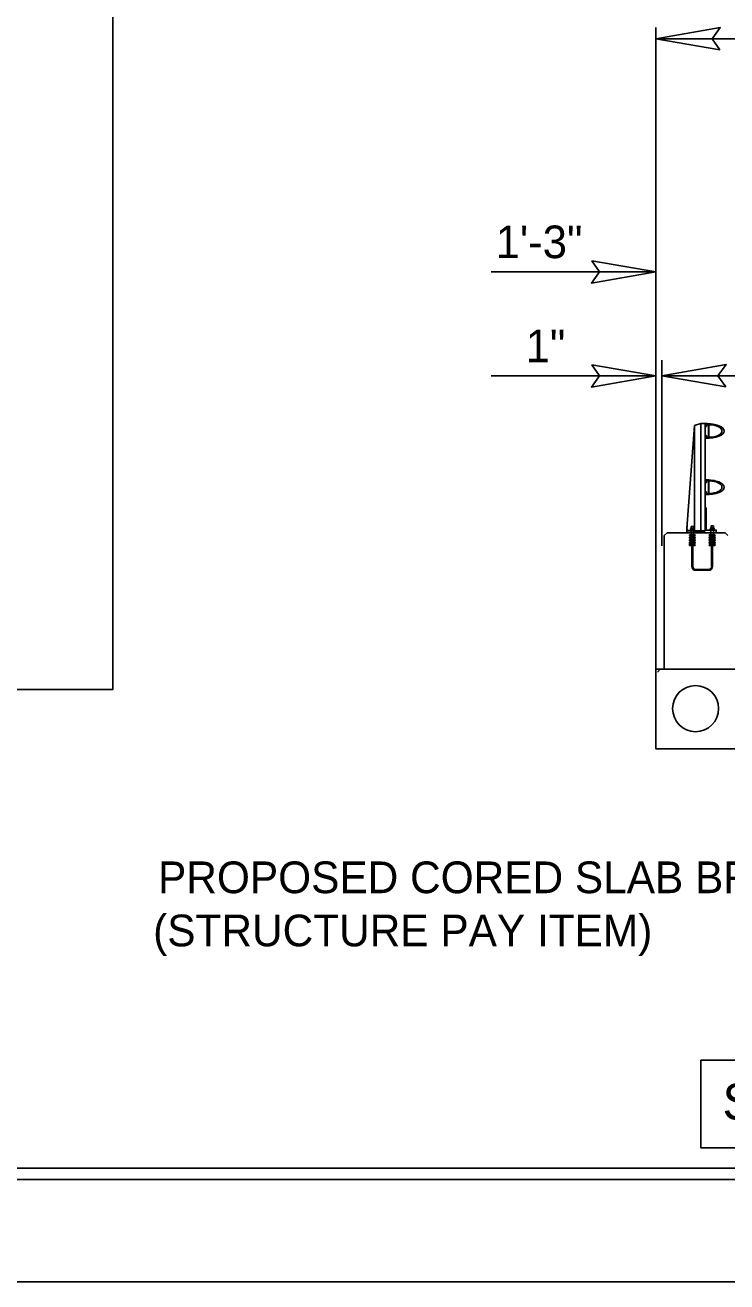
# Model space of a CAD drawing. Extents: x 1718167 to 1721223, y 797898 to 799800.
# Drawn here: x 1719514 to 1719668.1, y 798024.4 to 798300.3 of the extents above; entities that cross this region are included whole.
import ezdxf

# ---------------------------------------------------------------- set-up
doc = ezdxf.new("R2010")
doc.units = 0
for name, color, linetype in [('Default', 7, 'Continuous'), ('Old_Level_1', 7, 'Continuous'), ('Old_Level_18', 7, 'Continuous'), ('Old_Level_2', 7, 'Continuous'), ('Old_Level_3', 7, 'Continuous'), ('Sheet Cutting Line CELL', 7, 'Continuous'), ('Sheet Plot Border Inside CELL', 7, 'Continuous'), ('Sheet Plot Border Outside CELL', 7, 'Continuous'), ('Sheet Typical CELL', 7, 'Continuous'), ('Typical Bridge Rail Two Bar CELL', 7, 'Continuous'), ('Typical Slope Point Local CELL', 7, 'Continuous'), ('Typical Terminator CELL', 7, 'Continuous'), ('Typical Text Label CELL', 7, 'Continuous')]:
    doc.layers.add(name, color=color, linetype=linetype)

msp = doc.modelspace()

# ---------------------------------------------------------------- linework, layer by layer
at = {"layer": 'Old_Level_1'}
for p, q in [((1719652.48, 798158.9), (1719978.23, 798158.9)), ((1719652.48, 798158.9), (1719652.48, 798141.4)), ((1719652.48, 798141.4), (1719978.23, 798141.4))]:
    msp.add_line(p, q, dxfattribs=at)
at = {"layer": 'Old_Level_18'}
msp.add_circle((1719661.21, 798150.23), 5.06, dxfattribs=at)
at = {"layer": 'Old_Level_2'}
for p, q in [((1719652.48, 798299.76), (1719652.48, 798158.26)), ((1719978.22, 798297.26), (1719652.48, 798297.26)), ((1719652.48, 798246.15), (1719616.3, 798246.15)), ((1719653.77, 798185.98), (1719653.77, 798226.74)), ((1719652.48, 798223.31), (1719616.3, 798223.31)), ((1719672.97, 798223.31), (1719653.77, 798223.31))]:
    msp.add_line(p, q, dxfattribs=at)
at = {"layer": 'Sheet Cutting Line CELL'}
msp.add_line((1718866, 798024.37), (1720550, 798024.37), dxfattribs=at)
at = {"layer": 'Sheet Plot Border Inside CELL'}
msp.add_lwpolyline([(1720545.5, 799101.92), (1718879, 799101.92), (1718879, 798046.82), (1720545.5, 798046.82)], close=True, dxfattribs=at)
at = {"layer": 'Sheet Plot Border Outside CELL'}
msp.add_lwpolyline([(1720550, 799124.37), (1718866, 799124.37), (1718866, 798024.37), (1720550, 798024.37)], close=True, dxfattribs=at)
at = {"layer": 'Sheet Typical CELL'}
msp.add_lwpolyline([(1720533, 799099.37), (1719033, 799099.37), (1719033, 798049.37), (1720533, 798049.37)], close=True, dxfattribs=at)
at = {"layer": 'Typical Bridge Rail Two Bar CELL'}
for p, q in [((1719660.97, 798212.38), (1719659.32, 798189.77)), ((1719660.97, 798212.38), (1719662.39, 798212.85)), ((1719660.97, 798189.3), (1719660.97, 798212.38)), ((1719663.33, 798212.85), (1719662.39, 798212.85)), ((1719662.39, 798189.3), (1719662.39, 798212.85)), ((1719663.33, 798189.3), (1719663.33, 798212.85)), ((1719664.12, 798212.46), (1719664.12, 798211.18)), ((1719664.12, 798209.9), (1719664.12, 798211.18)), ((1719660.97, 798201.58), (1719660.91, 798201.58)), ((1719664.12, 798200.12), (1719664.12, 798198.84)), ((1719664.12, 798197.56), (1719664.12, 798198.84)), ((1719654.34, 798188.22), (1719654.95, 798188.83)), ((1719667.71, 798188.83), (1719654.95, 798188.83)), ((1719659.32, 798189.3), (1719659.32, 798189.77)), ((1719659.37, 798190.04), (1719659.37, 798190.45)), ((1719660.23, 798188.26), (1719660.23, 798189.3)), ((1719660.78, 798190.25), (1719660.24, 798190.25)), ((1719660.24, 798190.25), (1719660.24, 798189.81)), ((1719660.77, 798188.26), (1719660.77, 798189.3)), ((1719660.78, 798189.81), (1719660.78, 798190.25)), ((1719664.57, 798188.38), (1719664.57, 798189.42)), ((1719665.14, 798190.38), (1719664.6, 798190.38)), ((1719664.6, 798190.38), (1719664.6, 798189.93)), ((1719665.14, 798189.93), (1719665.14, 798190.38)), ((1719665.16, 798188.38), (1719665.16, 798189.42)), ((1719667.71, 798188.83), (1719668.32, 798188.22)), ((1719654.34, 798188.22), (1719654.34, 798158.91)), ((1719661.12, 798188.38), (1719659.87, 798188.38)), ((1719661.12, 798188.24), (1719659.87, 798188.24)), ((1719660.39, 798187.82), (1719659.87, 798187.82)), ((1719660.39, 798187.69), (1719659.87, 798187.69)), ((1719660.39, 798187.27), (1719659.87, 798187.27)), ((1719660.39, 798187.13), (1719659.87, 798187.13)), ((1719660.39, 798186.71), (1719659.87, 798186.71)), ((1719660.39, 798186.58), (1719659.87, 798186.58)), ((1719660.39, 798186.16), (1719659.87, 798186.16)), ((1719660.39, 798186.02), (1719659.87, 798186.02)), ((1719660.39, 798188.1), (1719660.14, 798188.1)), ((1719660.39, 798187.96), (1719660.14, 798187.96)), ((1719660.39, 798187.54), (1719660.14, 798187.54)), ((1719660.39, 798187.41), (1719660.14, 798187.41)), ((1719660.39, 798186.99), (1719660.14, 798186.99)), ((1719660.39, 798186.85), (1719660.14, 798186.85)), ((1719660.39, 798186.43), (1719660.14, 798186.43)), ((1719660.39, 798186.3), (1719660.14, 798186.3)), ((1719660.6, 798188.1), (1719660.39, 798188.1)), ((1719660.39, 798188.1), (1719660.39, 798181.47)), ((1719660.84, 798188.1), (1719660.6, 798188.1)), ((1719660.6, 798188.1), (1719660.6, 798181.47)), ((1719660.84, 798187.96), (1719660.6, 798187.96)), ((1719661.12, 798187.82), (1719660.6, 798187.82)), ((1719661.12, 798187.69), (1719660.6, 798187.69)), ((1719660.84, 798187.54), (1719660.6, 798187.54)), ((1719660.84, 798187.41), (1719660.6, 798187.41)), ((1719661.12, 798187.27), (1719660.6, 798187.27)), ((1719661.12, 798187.13), (1719660.6, 798187.13)), ((1719660.84, 798186.99), (1719660.6, 798186.99)), ((1719660.84, 798186.85), (1719660.6, 798186.85)), ((1719661.12, 798186.71), (1719660.6, 798186.71)), ((1719661.12, 798186.58), (1719660.6, 798186.58)), ((1719660.84, 798186.43), (1719660.6, 798186.43)), ((1719660.84, 798186.3), (1719660.6, 798186.3)), ((1719661.12, 798186.16), (1719660.6, 798186.16)), ((1719661.12, 798186.02), (1719660.6, 798186.02)), ((1719665.47, 798188.38), (1719664.22, 798188.38)), ((1719665.47, 798188.24), (1719664.22, 798188.24)), ((1719664.74, 798187.82), (1719664.22, 798187.82)), ((1719664.74, 798187.69), (1719664.22, 798187.69)), ((1719664.74, 798187.27), (1719664.22, 798187.27)), ((1719664.74, 798187.13), (1719664.22, 798187.13)), ((1719664.74, 798186.71), (1719664.22, 798186.71)), ((1719664.74, 798186.58), (1719664.22, 798186.58)), ((1719664.74, 798186.16), (1719664.22, 798186.16)), ((1719664.74, 798186.02), (1719664.22, 798186.02)), ((1719664.74, 798188.1), (1719664.5, 798188.1)), ((1719664.74, 798187.96), (1719664.5, 798187.96)), ((1719664.74, 798187.54), (1719664.5, 798187.54)), ((1719664.74, 798187.41), (1719664.5, 798187.41)), ((1719664.74, 798186.99), (1719664.5, 798186.99)), ((1719664.74, 798186.85), (1719664.5, 798186.85)), ((1719664.74, 798186.43), (1719664.5, 798186.43)), ((1719664.74, 798186.3), (1719664.5, 798186.3)), ((1719664.95, 798188.1), (1719664.74, 798188.1)), ((1719664.74, 798188.1), (1719664.74, 798181.47)), ((1719665.2, 798188.1), (1719664.95, 798188.1)), ((1719664.95, 798188.1), (1719664.95, 798181.47)), ((1719665.2, 798187.96), (1719664.95, 798187.96)), ((1719665.47, 798187.82), (1719664.95, 798187.82)), ((1719665.47, 798187.69), (1719664.95, 798187.69)), ((1719665.2, 798187.54), (1719664.95, 798187.54)), ((1719665.2, 798187.41), (1719664.95, 798187.41)), ((1719665.47, 798187.27), (1719664.95, 798187.27)), ((1719665.47, 798187.13), (1719664.95, 798187.13)), ((1719665.2, 798186.99), (1719664.95, 798186.99)), ((1719665.2, 798186.85), (1719664.95, 798186.85)), ((1719665.47, 798186.71), (1719664.95, 798186.71)), ((1719665.47, 798186.58), (1719664.95, 798186.58)), ((1719665.2, 798186.43), (1719664.95, 798186.43)), ((1719665.2, 798186.3), (1719664.95, 798186.3)), ((1719665.47, 798186.16), (1719664.95, 798186.16)), ((1719665.47, 798186.02), (1719664.95, 798186.02)), ((1719664.08, 798180.8), (1719661.26, 798180.8)), ((1719664.08, 798180.6), (1719661.26, 798180.6)), ((1719652.84, 798158.25), (1719653.45, 798158.91)), ((1719654.46, 798158.91), (1719653.45, 798158.91)), ((1719668.32, 798158.91), (1719654.46, 798158.91))]:
    msp.add_line(p, q, dxfattribs=at)
for points in [[(1719663.33, 798209.55), (1719663.33, 798210.16), (1719663.58, 798210.16), (1719663.58, 798210.06), (1719663.56, 798210.06), (1719663.56, 798209.8), (1719663.97, 798209.8), (1719664.02, 798210.19), (1719664.02, 798211.18), (1719664.02, 798212.16), (1719663.97, 798212.56), (1719663.56, 798212.56), (1719663.56, 798212.3), (1719663.58, 798212.3), (1719663.58, 798212.2), (1719663.33, 798212.2), (1719663.33, 798212.81)], [(1719663.33, 798197.21), (1719663.33, 798197.82), (1719663.58, 798197.82), (1719663.58, 798197.72), (1719663.56, 798197.72), (1719663.56, 798197.46), (1719663.97, 798197.46), (1719664.02, 798197.86), (1719664.02, 798198.84), (1719664.02, 798199.82), (1719663.97, 798200.21), (1719663.56, 798200.21), (1719663.56, 798199.96), (1719663.58, 798199.96), (1719663.58, 798199.86), (1719663.33, 798199.86), (1719663.33, 798200.47)], [(1719665.74, 798188.83), (1719665.74, 798189.42), (1719663.57, 798189.42), (1719663.57, 798194.25), (1719663.33, 798194.25), (1719663.33, 798189.3), (1719659.43, 798189.3), (1719659.43, 798189.65), (1719659.32, 798189.65), (1719659.32, 798188.83), (1719661.2, 798188.83), (1719661.2, 798189.16), (1719663.1, 798189.16), (1719663.1, 798188.83), (1719665.74, 798188.83)], [(1719661.04, 798189.3), (1719661.04, 798189.4), (1719660.5, 798189.4), (1719659.97, 798189.4), (1719659.97, 798189.3)], [(1719660.9, 798189.4), (1719660.9, 798189.75), (1719660.84, 798189.81), (1719660.18, 798189.81), (1719660.11, 798189.75), (1719660.11, 798189.4), (1719660.9, 798189.4), (1719660.64, 798189.4), (1719660.64, 798189.75), (1719660.71, 798189.81), (1719660.64, 798189.75), (1719660.58, 798189.81), (1719660.44, 798189.81), (1719660.37, 798189.75), (1719660.37, 798189.4), (1719660.37, 798189.75), (1719660.3, 798189.81)], [(1719665.41, 798189.42), (1719665.41, 798189.52), (1719664.87, 798189.52), (1719664.34, 798189.52), (1719664.34, 798189.42)], [(1719665.26, 798189.52), (1719665.26, 798189.86), (1719665.2, 798189.93), (1719664.54, 798189.93), (1719664.47, 798189.86), (1719664.47, 798189.52), (1719665.26, 798189.52), (1719665, 798189.52), (1719665, 798189.86), (1719665.07, 798189.93), (1719665, 798189.86), (1719664.93, 798189.93), (1719664.8, 798189.93), (1719664.73, 798189.86), (1719664.73, 798189.52), (1719664.73, 798189.86), (1719664.67, 798189.93)], [(1719659.87, 798188.38), (1719659.87, 798188.24), (1719660.14, 798188.1), (1719660.14, 798187.96), (1719659.87, 798187.82), (1719659.87, 798187.69), (1719660.14, 798187.54), (1719660.14, 798187.41), (1719659.87, 798187.27), (1719659.87, 798187.13), (1719660.14, 798186.99), (1719660.14, 798186.85), (1719659.87, 798186.71), (1719659.87, 798186.58), (1719660.14, 798186.43), (1719660.14, 798186.3), (1719659.87, 798186.16), (1719659.87, 798186.02)], [(1719661.12, 798188.38), (1719661.12, 798188.24), (1719660.84, 798188.1), (1719660.84, 798187.96), (1719661.12, 798187.82), (1719661.12, 798187.69), (1719660.84, 798187.54), (1719660.84, 798187.41), (1719661.12, 798187.27), (1719661.12, 798187.13), (1719660.84, 798186.99), (1719660.84, 798186.85), (1719661.12, 798186.71), (1719661.12, 798186.58), (1719660.84, 798186.43), (1719660.84, 798186.3), (1719661.12, 798186.16), (1719661.12, 798186.02)], [(1719664.22, 798188.38), (1719664.22, 798188.24), (1719664.5, 798188.1), (1719664.5, 798187.96), (1719664.22, 798187.82), (1719664.22, 798187.69), (1719664.5, 798187.54), (1719664.5, 798187.41), (1719664.22, 798187.27), (1719664.22, 798187.13), (1719664.5, 798186.99), (1719664.5, 798186.85), (1719664.22, 798186.71), (1719664.22, 798186.58), (1719664.5, 798186.43), (1719664.5, 798186.3), (1719664.22, 798186.16), (1719664.22, 798186.02)], [(1719665.48, 798188.38), (1719665.48, 798188.24), (1719665.2, 798188.1), (1719665.2, 798187.96), (1719665.48, 798187.82), (1719665.48, 798187.69), (1719665.2, 798187.54), (1719665.2, 798187.41), (1719665.48, 798187.27), (1719665.48, 798187.13), (1719665.2, 798186.99), (1719665.2, 798186.85), (1719665.48, 798186.71), (1719665.48, 798186.58), (1719665.2, 798186.43), (1719665.2, 798186.3), (1719665.48, 798186.16), (1719665.48, 798186.02)]]:
    msp.add_lwpolyline(points, dxfattribs=at)
for centre in [(1719659.98, 798186.37), (1719665.37, 798186.37)]:
    msp.add_circle(centre, 0.104, dxfattribs=at)
for centre, radius, start, end in [((1719664.22, 798212.46), 0.0979, 90, 180), ((1719664.22, 798209.9), 0.0979, 180, 270), ((1719664.22, 798200.12), 0.0979, 90, 180), ((1719664.22, 798197.56), 0.0979, 180, 270), ((1719661.26, 798181.47), 0.876, 180, 270), ((1719661.26, 798181.47), 0.667, 180, 270), ((1719664.08, 798181.47), 0.667, 270, 0), ((1719664.08, 798181.47), 0.876, 270, 0)]:
    msp.add_arc(centre, radius, start, end, dxfattribs=at)
for centre, major_axis, ratio, start_param, end_param in [((1719663.33, 798211.18), (4.18, 0), 0.39036, 6.282787, 7.853967), ((1719663.33, 798211.18), (4.18, 0), 0.39036, 4.712404, 6.282787), ((1719664.22, 798211.18), (2.78, 0), 0.495501, 6.282718, 7.853881), ((1719664.22, 798211.18), (2.78, 0), 0.495501, 4.712489, 6.282718), ((1719663.33, 798198.84), (4.18, 0), 0.39036, 6.282787, 7.853967), ((1719664.22, 798198.84), (2.78, 0), 0.495501, 6.282718, 7.853881), ((1719663.33, 798198.84), (4.18, 0), 0.39036, 4.712404, 6.282787), ((1719664.22, 798198.84), (2.78, 0), 0.495501, 4.712489, 6.282718)]:
    msp.add_ellipse(centre, major_axis=major_axis, ratio=ratio, start_param=start_param, end_param=end_param, dxfattribs=at)
at = {"layer": 'Typical Slope Point Local CELL'}
msp.add_lwpolyline([(1719060.96, 798154.41), (1719533.22, 798154.41), (1719533.22, 798415.08), (1719060.96, 798415.08)], close=True, dxfattribs=at)
at = {"layer": 'Typical Terminator CELL'}
for points in [[(1719666.54, 798294.84), (1719652.48, 798297.26), (1719666.62, 798299.76), (1719664.82, 798297.26)], [(1719638.42, 798248.57), (1719652.48, 798246.15), (1719638.34, 798243.65), (1719640.14, 798246.15)], [(1719638.42, 798225.73), (1719652.48, 798223.31), (1719638.34, 798220.81), (1719640.14, 798223.31)], [(1719667.83, 798220.89), (1719653.77, 798223.31), (1719667.9, 798225.81), (1719666.11, 798223.31)]]:
    msp.add_lwpolyline(points, close=True, dxfattribs=at)
at = {"layer": 'Typical Text Label CELL'}
msp.add_lwpolyline([(1719662.34, 798073.04), (1719992.26, 798073.04), (1719992.26, 798053.81), (1719662.34, 798053.81)], close=True, dxfattribs=at)

# ---------------------------------------------------------------- texts
at = {"layer": 'Default'}
msp.add_text('SR 1193, BAKER RD IS A DESIGNATED BICYCLE ROUTE NO. 5', height=8, dxfattribs=at).set_placement((1719667.13, 798059.94))
at = {"layer": 'Old_Level_1'}
msp.add_text('1\'-3"', height=7.161, dxfattribs=at).set_placement((1719617.3, 798249.13))
msp.add_text('1"', height=7.161, rotation=360, dxfattribs=at).set_placement((1719623.89, 798226.29))
at = {"layer": 'Old_Level_18'}
msp.add_text('(STRUCTURE PAY ITEM)', height=6.9609, dxfattribs=at).set_placement((1719542.08, 798098.04))
at = {"layer": 'Old_Level_3'}
msp.add_text('PROPOSED CORED SLAB BRIDGE', height=6.9609, dxfattribs=at).set_placement((1719543.16, 798109.71))

doc.saveas('drawing.dxf')
